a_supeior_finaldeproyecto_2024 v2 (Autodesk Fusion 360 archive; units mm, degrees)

design "a_supeior_finaldeproyecto_2024" references "b_superior_lado izquierdo-d", "b_superior_adelente"
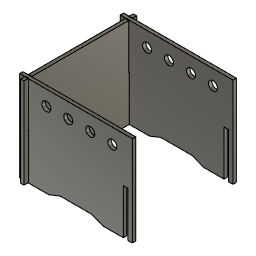
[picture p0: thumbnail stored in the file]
component_insert "Component Insert1"
component_insert "Component Insert2"
component_insert "Component Insert3"

design "b_superior_lado izquierdo-d"
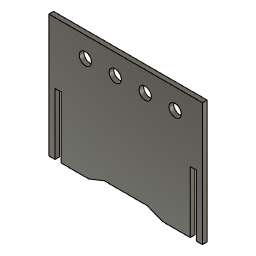
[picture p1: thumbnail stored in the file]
sketch "Sketch1" plane through (0, 0, 0) normal (0, 1, 0) x axis (1, 0, 0)
  line L1 (500, -400) -> (500, 0)
  line L2 (0, -400) -> (500, -400)
  line L3 (0, 0) -> (0, -400)
  line L4 (320, -20) -> (250, -20)
  line L5 (180, -20) -> (250, -20)
  line L6 (370.02, 0) -> (460, 0)
  line L7 (180, -20) -> (129.98, 0)
  line L8 (370.02, 0) -> (320, -20)
  line L9 (129.98, 0) -> (20, 0)
  line L10 (20, -200) -> (20, 0)
  line L11 (480, -200) -> (480, 0)
  line L12 (40, -200) -> (40, 0)
  line L13 (20, -200) -> (40, -200)
  line L14 (20, 0) -> (20, -200)
  line L15 (460, -200) -> (460, 0)
  line L16 (480, -200) -> (460, -200)
  line L17 (480, 0) -> (480, -200)
  line L18 (20, 0) -> (0, 0)
  line L19 (480, 0) -> (500, 0)
  point P1 (0, 0)
  point P2 (0, 0)
  point P22 (0, 0)
  point P5 (0, -400)
  point P6 (20, 0)
  point P11 (129.98, 0)
  point P14 (20, -200)
  point P13 (480, 0)
  point P15 (480, -200)
  point P18 (20, -200)
  point P7 (480, 0)
  point P21 (480, -200)
  vertical L1
  horizontal L2
  vertical L3
  coincident P1 P2
  vertical L12
  horizontal L13
  vertical L14
  vertical L15
  horizontal L16
  vertical L17
  coincident P1 P22
  perpendicular L14 L18
  perpendicular L11 L19
  dimension "d2" distance P2 P5 = 400
  dimension "d8" distance P6 P11 = 109.98
  dimension "d11" distance P6 P14 = 200
  dimension "d12" distance P13 P15 = 200
  dimension "d14" distance P6 P18 = 200
  dimension "d16" distance P7 P21 = 200
extrude "Extrude1" new body sketch "Sketch1" along normal blind 15
sketch "Sketch2" plane through (0, 0, 0) normal (0, -1, 0) x axis (1, 0, 0)
  line L1 (500, 400) -> (500, 0)
  line L2 (0, 400) -> (500, 400)
  line L3 (0, 0) -> (0, 400)
  line L4 (20, 0) -> (0, 0)
  line L5 (20, 200) -> (20, 0)
  line L6 (40, 200) -> (20, 200)
  line L7 (40, 0) -> (40, 200)
  line L8 (129.98, 0) -> (40, 0)
  line L9 (180, 20) -> (129.98, 0)
  line L10 (320, 20) -> (180, 20)
  line L11 (370.02, 0) -> (320, 20)
  line L12 (460, 0) -> (370.02, 0)
  line L13 (460, 200) -> (460, 0)
  line L14 (480, 200) -> (460, 200)
  line L15 (480, 0) -> (480, 200)
  line L16 (500, 0) -> (480, 0)
  line L17 (118.9633, 333.53) -> (118.75, 333.53)
  circle C1 centre (118.75, 333.53) radius 20
  circle C2 centre (215.9, 333.53) radius 20
  circle C3 centre (313.41, 333.53) radius 20
  circle C4 centre (410.92, 333.53) radius 20
  point P19 (118.75, 333.53)
  point P20 (118.75, 333.53)
  point P21 (215.9, 333.53)
  point P22 (313.41, 333.53)
  point P23 (410.92, 333.53)
  coincident P19 P20
  dimension "d21" diameter C1 = 40
  dimension "d22" distance P20 P21 = 97.15
  dimension "d23" diameter C2 = 40
  dimension "d24" distance P21 P22 = 97.51
  dimension "d25" diameter C3 = 40
  dimension "d26" distance P22 P23 = 97.51
  dimension "d27" diameter C4 = 40
extrude "Extrude2" cut sketch "Sketch2" profile of C1 C2 C3 C4 distance 20

design "b_superior_adelente"
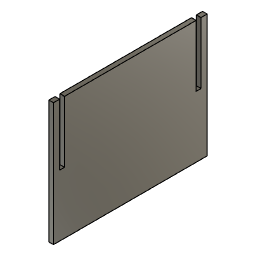
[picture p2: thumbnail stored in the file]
sketch "Sketch1" plane through (0, 0, 0) normal (1, 0, 0) x axis (0, 1, 0)
  line L1 (-483.5185, 0) -> (-483.5185, 400)
  line L2 (16.4815, 0) -> (-483.5185, 0)
  line L3 (16.4815, 400) -> (16.4815, 0)
  line L4 (-19.2685, 200) -> (-19.2685, 400)
  line L5 (-3.5185, 200) -> (-19.2685, 200)
  line L6 (-3.5185, 400) -> (-3.5185, 200)
  line L7 (-463.5185, 400) -> (-483.5185, 400)
  line L8 (-463.5185, 200) -> (-463.5185, 400)
  line L9 (-483.5185, 400) -> (-483.5185, 200)
  line L10 (-447.7685, 200) -> (-463.5185, 200)
  line L11 (-447.7685, 400) -> (-447.7685, 200)
  line L12 (-463.5185, 200) -> (-463.5185, 400)
  line L13 (-483.5185, 400) -> (-463.5185, 400)
  line L14 (-3.5185, 400) -> (16.4815, 400)
  line L15 (-447.7685, 400) -> (-19.2685, 400)
  point P2 (16.4815, 400)
  point P3 (-483.5185, 400)
  point P5 (16.4815, 0)
  point P6 (-3.5185, 400)
  point P7 (-19.2685, 400)
  point P9 (-3.5185, 200)
  point P10 (-463.5185, 400)
  point P12 (-483.5185, 200)
  point P11 (-463.5185, 200)
  point P13 (-447.7685, 200)
  point P15 (-463.5185, 400)
  horizontal L14
  vertical L1
  horizontal L2
  vertical L3
  vertical L4
  horizontal L5
  vertical L6
  horizontal L7
  vertical L8
  vertical L9
  horizontal L10
  vertical L11
  vertical L12
  collinear L13 L14
  collinear L14 L15
  dimension "d1" distance P2 P3 = 500
  dimension "d2" distance P2 P5 = 400
  dimension "d3" distance P6 P7 = 15.75
  dimension "d4" distance P6 P9 = 200
  dimension "d5" distance P3 P10 = 20
  dimension "d6" distance P3 P12 = 200
  dimension "d7" distance P11 P13 = 15.75
  dimension "d8" distance P11 P15 = 200
  dimension "d9" distance P2 P6 = 20
extrude "Extrude1" new body sketch "Sketch1" profile of L15 L1 L2 L3 L4 L5 L6 L7 L8 L9 L10 L11 L12 along normal blind 15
